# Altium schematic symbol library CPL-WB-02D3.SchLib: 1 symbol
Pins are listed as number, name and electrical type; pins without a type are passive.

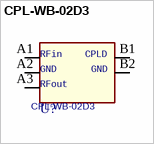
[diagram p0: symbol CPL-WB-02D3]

## CPL-WB-02D3
designator U?
footprint ST_CSP05N45P2X3_135X100X63-B3
pins: A1 RFin, A2 GND, A3 RFout, B1 CPLD, B2 GND1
